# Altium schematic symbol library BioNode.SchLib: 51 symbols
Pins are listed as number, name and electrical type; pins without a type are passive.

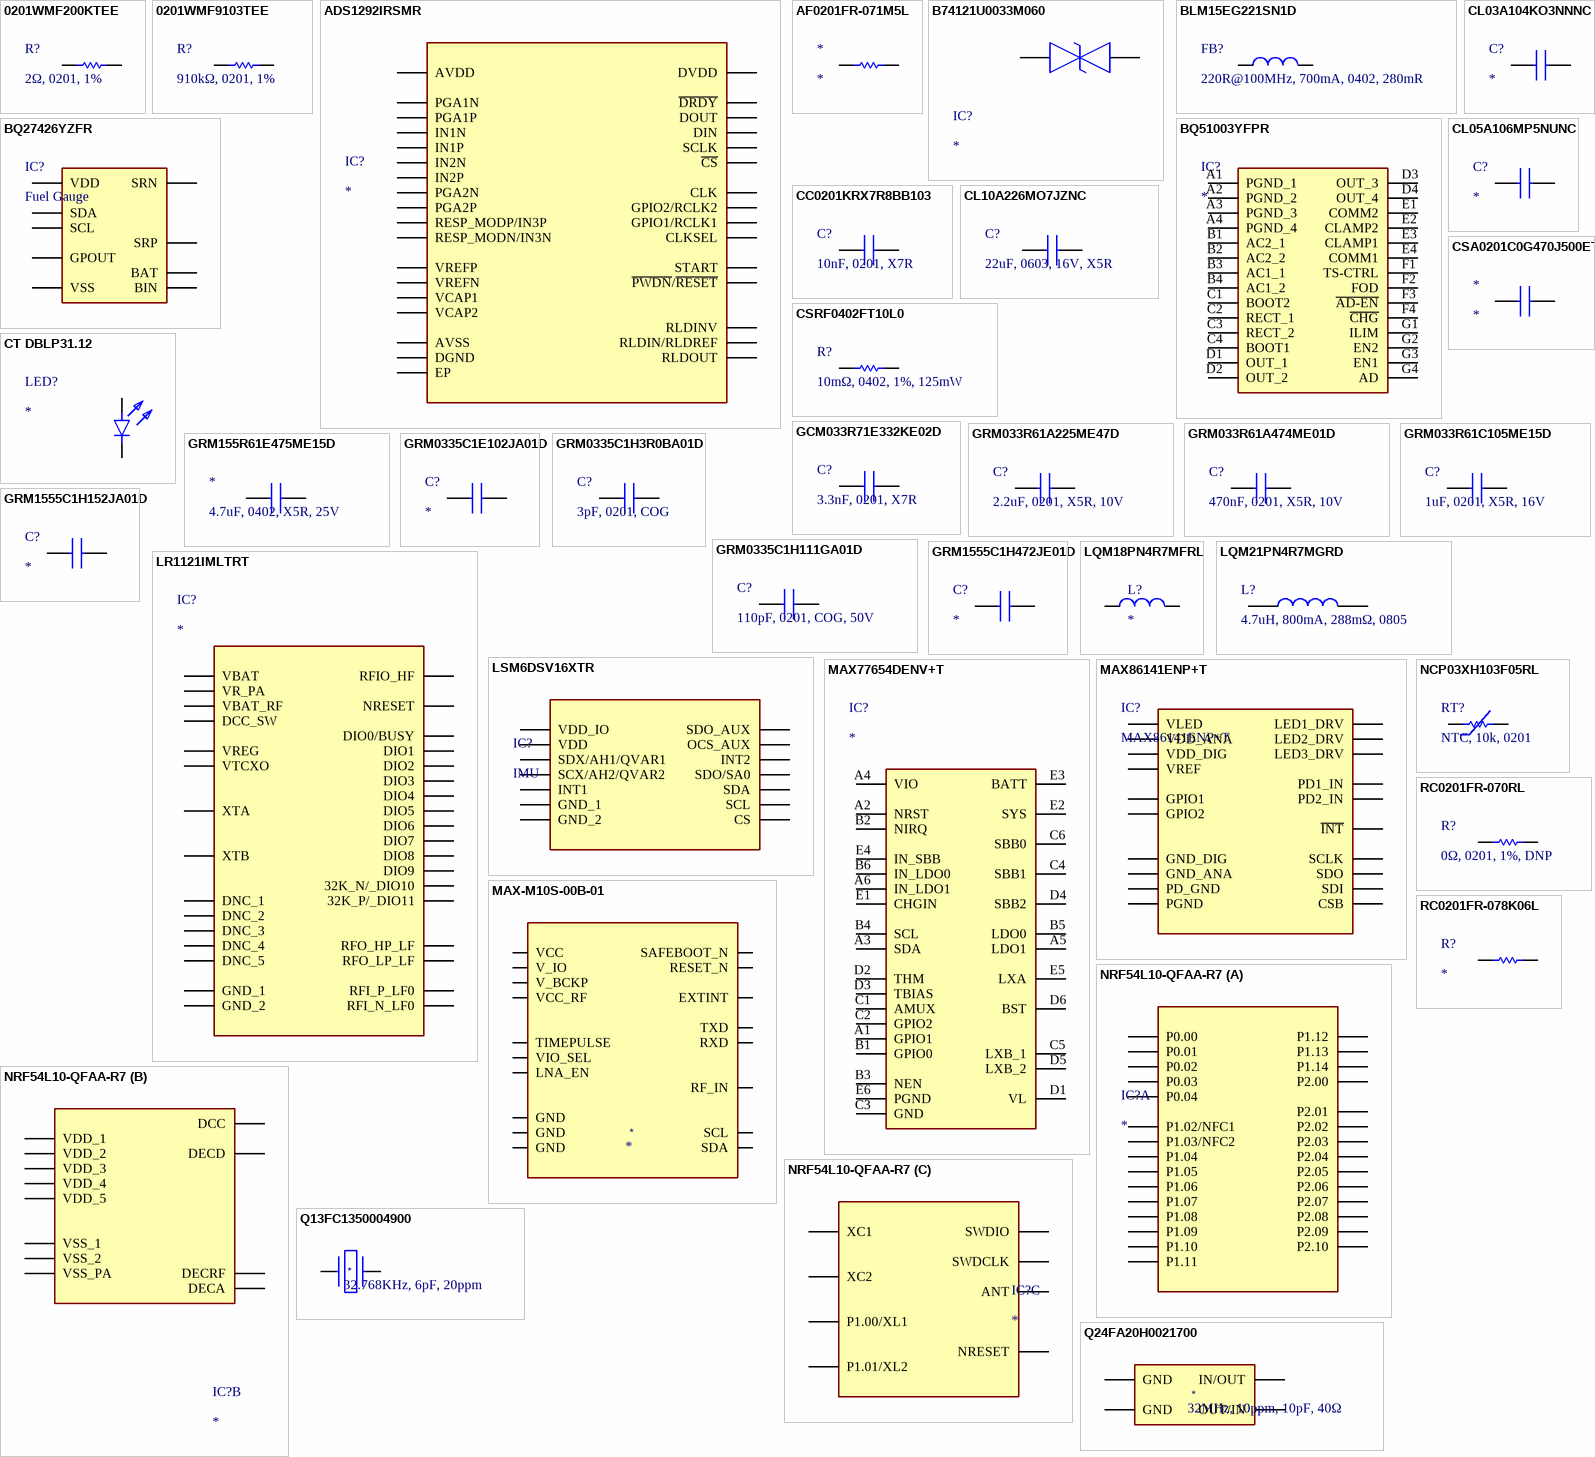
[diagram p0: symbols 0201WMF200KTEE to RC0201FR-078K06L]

## 0201WMF200KTEE
designator R?, comment 2Ω, 0201, 1%
2Ω ±1% 50mW 0201 Thick Film Resistor; Manufacturer_Name: UNI-ROYAL; Manu Part #: 0201WMF200KTEE
footprint 0201WMF200KTEE
pins: 1, 2

## 0201WMF9103TEE
designator R?, comment 910kΩ, 0201, 1%
RES 910kΩ ±1% 50mW 0201; Manufacturer_Name: UNI-ROYAL; Manu Part #: 0201WMF9103TEE
footprint 0201WMF9103TEE
pins: 1, 2

## ADS1292IRSMR
designator IC?
ECG AFE; Manufacturer_Name: Texas Instruments; Manufacturer_Part_Number: ADS1292IRSMR
footprint QFN40P400X400X100-33N-D
pins: 1 PGA1N, 2 PGA1P, 3 IN1N, 4 IN1P, 5 IN2N, 6 IN2P, 7 PGA2N, 8 PGA2P, 9 VREFP, 10 VREFN, 11 VCAP1, 12 AVDD, 13 AVSS, 14 CLKSEL, 15 ~{PWDN}/~{RESET}, 16 START, 17 CLK, 18 ~{CS}, 19 DIN, 20 SCLK, 21 DOUT, 22 ~{DRDY}, 23 DVDD, 24 DGND, 25 GPIO2/RCLK2, 26 GPIO1/RCLK1, 27 VCAP2, 28 RLDINV, 29 RLDIN/RLDREF, 30 RLDOUT, 31 RESP_MODP/IN3P, 32 RESP_MODN/IN3N, 33 EP

## AF0201FR-071M5L
designator *
1.5M, 0201. 1%; Manu Part #: AF0201FR-071M5L
footprint AF0201FR-071M5L
pins: 1, 2

## B74121U0033M060
designator IC?
-40℃~+125℃ 0.65pF 1 1nA 3.3V 5.2V 5V 7A@8/20us Bidirectional IEC 61000-4-2、IEC 61000-4-5 TVS 0201 ESD and Surge Protection (TVS/ESD) ROHS; Manufacturer_Name: TDK; Manu Part #: B74121U0033M060
footprint B74121U0033M060
pins: A1 I/O, B1 GND

## BLM15EG221SN1D
designator FB?, comment 220R@100MHz, 700mA, 0402, 280mR
BLM15_N1D Series EMI Suppression Filter 220+/-25% at 100MHz 700mA @85; Manufacturer_Name: Murata Electronics; Manu Part #: BLM15EG221SN1D
footprint NFZ15SG152SN10B
pins: 1, 2

## BQ27426YZFR
designator IC?, comment Fuel Gauge
Single cell System-Side Battery Fuel (Gas) Gauge w/Pre-programmed Chemistry Profile; Manufacturer_Name: Texas Instruments; Manu Part #: BQ27426YZFR
footprint BQ27426YZFR
pins: A1 GPOUT, A2 SDA, A3 SCL, B1 BIN, B2 VSS, B3 VDD, C1 SRP, C2 SRN, C3 BAT

## BQ51003YFPR
designator IC?
Integrated Circuit; Manufacturer_Name: Texas Instruments; Manufacturer_Part_Number: BQ51003YFPR
footprint BGA28C40P4X7_188X301X50
pins: A1 PGND_1, A2 PGND_2, A3 PGND_3, A4 PGND_4, B1 AC2_1, B2 AC2_2, B3 AC1_1, B4 AC1_2, C1 BOOT2, C2 RECT_1, C3 RECT_2, C4 BOOT1, D1 OUT_1, D2 OUT_2, D3 OUT_3, D4 OUT_4, E1 COMM2, E2 CLAMP2, E3 CLAMP1, E4 COMM1, F1 TS-CTRL, F2 FOD, F3 ~{AD-EN}, F4 ~{CHG}, G1 ILIM, G2 EN2, G3 EN1, G4 AD

## CC0201KRX7R8BB103
designator C?, comment 10nF, 0201, X7R
Manufacturer_Name: YAGEO; Manu Part #: CC0201KRX7R8BB103
footprint CL03A105MQ3CSNH
pins: 1, 2

## CL03A104KO3NNNC
designator C?
CAP CER 100nF 25V X5R 0201; Manufacturer_Name: SAMSUNG; Manu Part #: CL03A104KA3NNNC
footprint CL03A104KO3NNNC
pins: 1, 2

## CL05A106MP5NUNC
designator C?
10uF, 0402, X5R; Manufacturer_Name: SAMSUNG; Manu Part #: CL05A106MP5NUNC
footprint CL05A106MP5NUNC
pins: 1, 2

## CL10A226MO7JZNC
designator C?, comment 22uF, 0603, 16V, X5R
Multilayer Ceramic Capacitors MLCC - SMD/SMT 22uF+/-20% 16V X5R 1608; Manufacturer_Name: SAMSUNG; Manu Part #: CL10A226MO7JZNC
footprint CAPC1608X80N
pins: 1, 2

## CSA0201C0G470J500ET
designator *
47pF, 0201, COG, 5%; Manu Part #: CSA0201C0G470J500ET
footprint CSA0201C0G470J500ET
pins: 1, 2

## CSRF0402FT10L0
designator R?, comment 10mΩ, 0402, 1%, 125mW
RES 10mΩ ±1% 125mW 0402; Manufacturer_Name: Stackpole Electronics; Manu Part #: CSRF0402FT10L0
footprint CSRF0402FT10L0
pins: 1, 2

## CT DBLP31.12
designator LED?
Standard LEDs - SMD Green 536nm Firefly E2218; Manufacturer_Name: ams OSRAM; Manu Part #: CT DBLP31.12-6C5D-56-J6U6-20-R18
footprint CTDBLP31126C5D56J6U620R18
pins: 1 -VE, 2 +VE

## GCM033R71E332KE02D
designator C?, comment 3.3nF, 0201, X7R
Manufacturer_Name: Murata Electronics; Manu Part #: GCM033R71E332KE02D
footprint GCM033R71E332KE02D
pins: 1, 2

## GRM033R61A225ME47D
designator C?, comment 2.2uF, 0201, X5R, 10V
Manufacturer_Name: Murata Electronics; Manu Part #: GRM033R61A225ME47D
footprint GRM033R61A225ME47D
pins: 1, 2

## GRM033R61A474ME01D
designator C?, comment 470nF, 0201, X5R, 10V
470nF X5R ±20% 10V 0201 Ceramic Capacitors RoHS; Manufacturer_Name: muRata; Manu Part #: GRM033R61A474ME01D
footprint GRM033R61A474ME01D
pins: 1, 2

## GRM033R61C105ME15D
designator C?, comment 1uF, 0201, X5R, 16V
Manufacturer_Name: muRata; Manu Part #: GRM033R61C105ME15D
footprint GRM033R61C105ME15D
pins: 1, 2

## GRM155R61E475ME15D
designator *, comment 4.7uF, 0402, X5R, 25V
4.7uF ±20% 25V Ceramic Capacitor X5R 0402; Manu Part #: GRM155R61E475ME15D
footprint CL05A106MP5NUNC
pins: 1, 2

## GRM0335C1E102JA01D
designator C?
1nF, 0201, COG, 5%; Manufacturer_Name: Murata Electronics; Manu Part #: GRM0335C1E102JA01D
footprint GRM0335C1E102JA01D
pins: 1, 2

## GRM0335C1H3R0BA01D
designator C?, comment 3pF, 0201, COG
Manufacturer_Name: Murata Electronics; Manu Part #: GRM0335C1H3R0BA01D
footprint GRM0335C1H3R0BA01D
pins: 1, 2

## GRM0335C1H111GA01D
designator C?, comment 110pF, 0201, COG, 50V
110pF C0G ±2% 50V 0201 Ceramic Capacitors RoHS; Manu Part #: GRM0335C1H111GA01D
footprint GRM0335C1H111GA01D
pins: 1, 2

## GRM1555C1H152JA01D
designator C?
1.5nF, 0402, COG; Manufacturer_Name: Murata Electronics; Manu Part #: GRM1555C1H152JA01D
footprint GRM1555C1H152JA01D
pins: 1, 2

## GRM1555C1H472JE01D
designator C?
4.7nF, 0402, COG; Manufacturer_Name: Murata Electronics; Manu Part #: GRM1555C1H472JE01D
footprint GRM15x
pins: 1, 2

## LQM18PN4R7MFRL
designator L?
FIXED IND 4.7uH 620mA 440mΩ 0603; Manufacturer_Name: Murata Electronics; Manu Part #: LQM18PN4R7MFRL
footprint LQM18PH1R0MFRB
pins: 1, 2

## LQM21PN4R7MGRD
designator L?, comment 4.7uH, 800mA, 288mΩ, 0805
FIXED IND 4.7uH 800mA 288mΩ 0805; Manufacturer_Name: Murata Electronics; Manu Part #: LQM21PN4R7MGRD
footprint LQM21PHR47NG0D
pins: 1, 2

## LR1121IMLTRT
designator IC?
-108dBm -40℃~+85℃ 1.8V~3.7V 101.5Kbps 13dBm 150MHz~960MHz、1.9GHz~2.1GHz、2.4GHz~2.5GHz 26mA 7.8mA LoRa SPI transceiver QFN-32-EP(5x5) RF Transceiver ICs ROHS; Manufacturer_Name: SEMTECH; Manu Part #: LR1121IMLTRT
footprint QFN50P500X500X100-33N-D
pins: 1 VR_PA, 2 VBAT_RF, 3 VTCXO, 4 XTA, 5 XTB, 6 NRESET, 7 32K_P/_DIO11, 8 32K_N/_DIO10, 9 DIO9, 10 DIO8, 11 DIO7, 12 VREG, 13 GND_1, 14 DCC_SW, 15 VBAT, 16 DNC_1, 17 DNC_2, 18 DNC_3, 19 DIO6, 20 DIO5, 21 DIO4, 22 DIO3, 23 DIO2, 24 DIO1, 25 DIO0/BUSY, 26 RFIO_HF, 27 DNC_4, 28 DNC_5, 29 RFI_N_LF0, 30 RFI_P_LF0, 31 RFO_LP_LF, 32 RFO_HP_LF, 33 GND_2

## LSM6DSV16XTR
designator IC?, comment IMU
6-axis inertial measurement unit (IMU) and Al sensor with embedded sensor fusion, Qvar for high-end applications; Manufacturer_Name: STMicroelectronics; Manu Part #: LSM6DSV16XTR
footprint LSM6DSV16BXTR
pins: 1 SDO/SA0, 2 SDX/AH1/QVAR1, 3 SCX/AH2/QVAR2, 4 INT1, 5 VDD_IO, 6 GND_1, 7 GND_2, 8 VDD, 9 INT2, 10 OCS_AUX, 11 SDO_AUX, 12 CS, 13 SCL, 14 SDA

## MAX77654DENV+T
designator IC?
Power Management Specialised - PMIC Ultra Low Power PMIC w/ 3-Output SIMO + Linear Charger; Manufacturer_Name: Analog Devices; Manu Part #: MAX77654DENV+T
footprint BGA30C40P6X5_279X234X50
pins: A1 GPIO1, A2 NRST, A3 SDA, A4 VIO, A5 LDO1, A6 IN_LDO1, B1 GPIO0, B2 NIRQ, B3 NEN, B4 SCL, B5 LDO0, B6 IN_LDO0, C1 AMUX, C2 GPIO2, C3 GND, C4 SBB1, C5 LXB_1, C6 SBB0, D1 VL, D2 THM, D3 TBIAS, D4 SBB2, D5 LXB_2, D6 BST, E1 CHGIN, E2 SYS, E3 BATT, E4 IN_SBB, E5 LXA, E6 PGND

## MAX86141ENP+T
designator IC?
Optical Pulse Oximeter and Heart-Rate Sensor for Wearable Health; Manufacturer_Name: Analog Devices
footprint BGA20C40P5X4_205X185X50
pins: A1 VLED, A2 SCLK, A3 SDO, A4 SDI, A5 CSB, B1 LED3_DRV, B2 ~{INT}, B3 GPIO1, B4 GPIO2, B5 VREF, C1 LED2_DRV, C2 VDD_DIG, C3 GND_DIG, C4 GND_ANA, C5 PD_GND, D1 LED1_DRV, D2 VDD_ANA, D3 PGND, D4 PD2_IN, D5 PD1_IN

## MAX-M10S-00B-01
designator *
MAX-M10 RF Receiver BeiDou, Galileo, GLONASS, GPS, GNSS 1.561GHz, 1.575GHz, 1.602GHz -167dBm 921.6kbps Module; Manufacturer: U-BLOX; Manu Part #: MAX-M10S-00B-01
footprint MAX-M10S-00B-01
pins: 1 GND, 2 TXD, 3 RXD, 4 TIMEPULSE, 5 EXTINT, 6 V_BCKP, 7 V_IO, 8 VCC, 9 RESET_N, 10 GND, 11 RF_IN, 12 GND, 13 LNA_EN, 14 VCC_RF, 15 VIO_SEL, 16 SDA, 17 SCL, 18 SAFEBOOT_N

## NCP03XH103F05RL
designator RT?, comment NTC, 10k, 0201
THERMISTOR NTC 10kΩ 3380K 0201; Manufacturer_Name: Murata Electronics; Manu Part #: NCP03XH103F05RL
footprint NCP03XH103F05RL
pins: 1, 2

## NRF54L10-QFAA-R7
designator IC?
IC RF TxRx + MCU 802.15.4, Bluetooth Bluetooth v6.0, Matter, Thread 48-VFQFN Exposed Pad; Manufacturer_Name: Nordic Semiconductor; Manu Part #: NRF54L10-QFAA-R7
footprint NRF54L10-QFAA-R7
part A pins: 3 P1.02/NFC1, 4 P1.03/NFC2, 5 P1.04, 6 P1.05, 7 P1.06, 8 P1.07, 9 P1.08, 11 P2.00, 12 P2.01, 13 P2.02, 14 P2.03, 15 P2.04, 16 P2.05, 17 P2.06, 18 P2.07, 19 P2.08, 20 P2.09, 21 P2.10, 23 P0.00, 24 P0.01, 27 P0.02, 28 P0.03, 29 P0.04, 37 P1.09, 38 P1.10, 39 P1.11, 40 P1.12, 41 P1.13, 42 P1.14
part B pins: 10 VDD_1, 22 VDD_2, 32 VSS_PA, 33 DECRF, 36 VDD_3, 43 DECA, 44 VSS_1, 45 DECD, 46 DCC, 47 VDD_4, 48 VDD_5, 49 VSS_2
part C pins: 1 P1.00/XL1, 2 P1.01/XL2, 25 SWDIO, 26 SWDCLK, 30 NRESET, 31 ANT, 34 XC1, 35 XC2

## Q13FC1350004900
designator *, comment 32.768KHz, 6pF, 20ppm
-40℃~+85℃ 32.768kHz 6pF 70kΩ Crystal Oscillator ±20ppm SMD3215-2P Crystals ROHS; Manufacturer: Seiko Epson; Manu Part #: Q13FC13500049
footprint Q13FC1350004900
pins: 1, 2

## Q24FA20H0021700
designator *, comment 32MHz, 10ppm, 10pF, 40Ω
-40℃~+85℃ 10pF 32MHz 40Ω Crystal Oscillator ±10ppm ±20ppm SMD2520-4P Crystals ROHS; Manufacturer: Seiko Epson; Manu Part #: Q24FA20H00217
footprint Q24FA20H0021700
pins: 1 IN/OUT, 2 GND, 3 OUT/IN, 4 GND

## RC0201FR-070RL
designator R?, comment 0Ω, 0201, 1%, DNP
RES 0Ω ±1% 50mW 0201; Manufacturer_Name: YAGEO; Manu Part #: RC0201FR-070RL
footprint RC0201FR-070RL
pins: 1, 2

## RC0201FR-078K06L
designator R?
8.06k, 0201, 1%; Manufacturer_Name: Yageo Group; Manu Part #: RC0201FR-078K06L
footprint RC0201FR-078K06L
pins: 1, 2

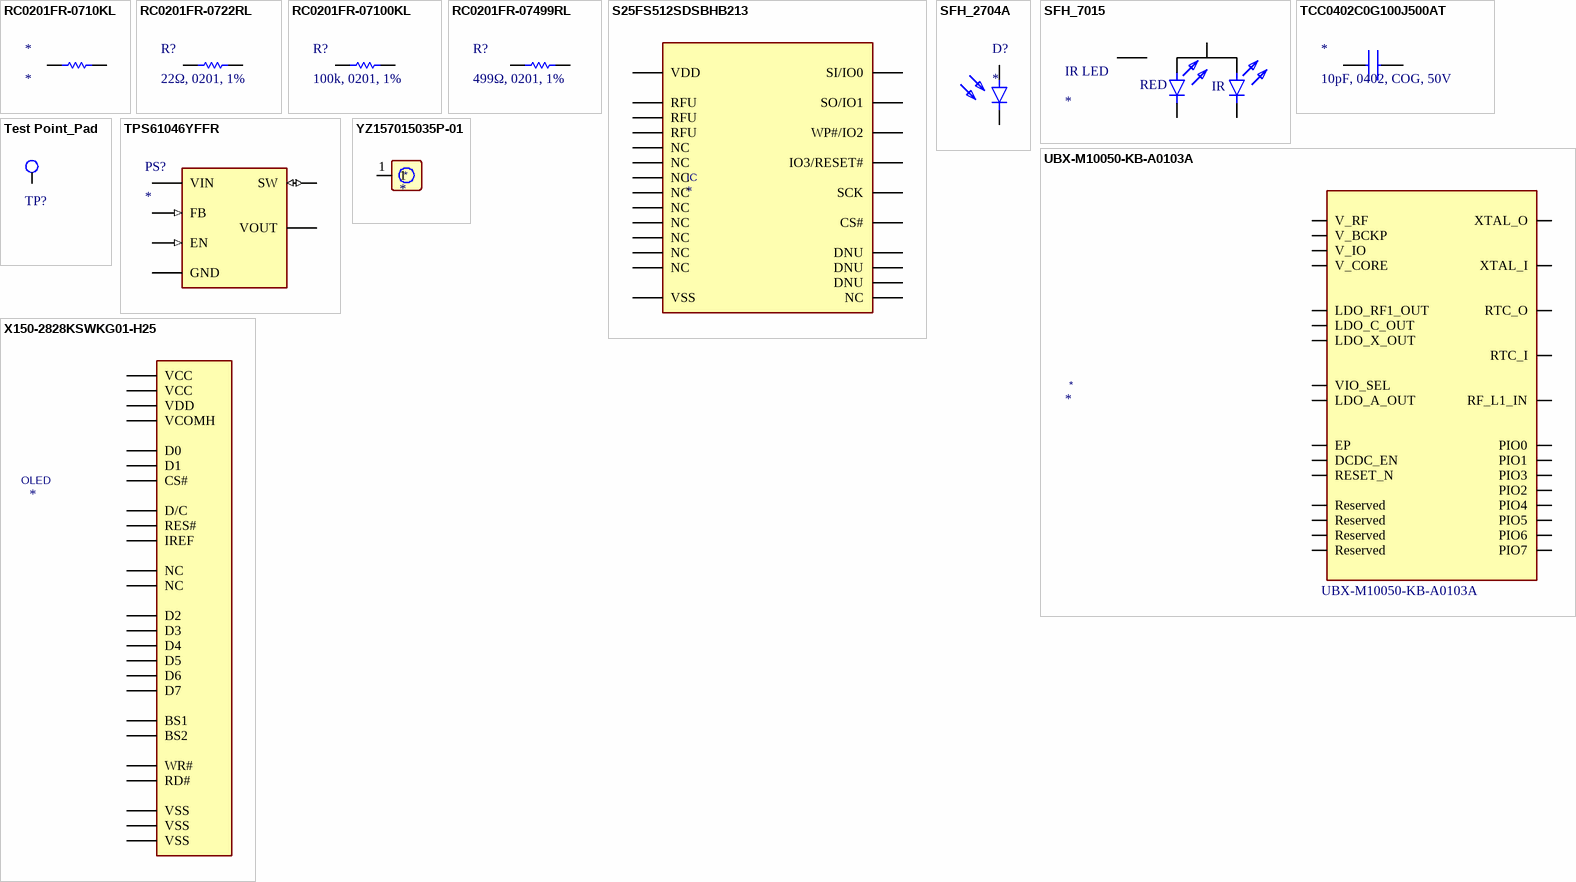
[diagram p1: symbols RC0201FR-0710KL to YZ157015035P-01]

## RC0201FR-0710KL
designator *
10k, 0201, 1%; Manu Part #: RC0201FR-0710KL
footprint RC0201FR-0710KL
pins: 1, 2

## RC0201FR-0722RL
designator R?, comment 22Ω, 0201, 1%
RES 22Ω ±1% 50mW 0201; Manu Part #: RC0201FR-0722RL
footprint AF0201FR-071M5L
pins: 1, 2

## RC0201FR-07100KL
designator R?, comment 100k, 0201, 1%
Manufacturer_Name: Yageo Group; Manu Part #: RC0201FR-07100KL
footprint RC0201FR-0710KL
pins: 1, 2

## RC0201FR-07499RL
designator R?, comment 499Ω, 0201, 1%
50mW 499Ω 25V Thick Film Resistor ±1% ±200ppm/℃ 0201 Chip Resistor - Surface Mount RoHS; Manufacturer_Name: Yageo Group; Manu Part #: RC0201FR-07499RL
footprint RC0201FR-07499RL
pins: 1, 2

## S25FS512SDSBHB213
designator IC
-40℃~+105℃ 1.7V~2V 512Mbit SPI TBGA-24 NOR FLASH ROHS; Manufacturer: Infineon/Cypress Semicon; Manu Part #: S25FS512SDSBHB213
footprint S25FS512SDSBHB213
pins: A2 NC, A3 NC, A4 RFU, A5 NC, B1 DNU, B2 SCK, B3 VSS, B4 VDD, B5 NC, C1 DNU, C2 CS#, C3 RFU, C4 WP#/IO2, C5 NC, D1 DNU, D2 SO/IO1, D3 SI/IO0, D4 IO3/RESET#, D5 NC, E1 NC, E2 NC, E3 NC, E4 RFU, E5 NC

## SFH_2704A
designator D?
Photodiodes FOR VITAL SIGNALMONITORING ,920nm ,400nm ~ 1100nm ,150pA ,6v .; Manufacturer_Name: ams OSRAM; Manu Part #: SFH 2704A
footprint SFH2704A
pins: 1 K, 2 A

## SFH_7015
designator IR LED
Red (655 nm) and Infrared Emitter (940 nm); Manufacturer_Name: ams OSRAM
footprint SFH7015
pins: 1 NC, 2 RED -VE, 3 VCC, 4 IR -VE

## TCC0402C0G100J500AT
designator *, comment 10pF, 0402, COG, 50V
10pF ±5% 50V Ceramic Capacitor C0G 0402; Manu Part #: TCC0402C0G100J500AT
footprint GRM15x
pins: 1, 2

## Test Point_Pad
designator TP?
2mm Pad
footprint Test_Pad
pins: 0

## TPS61046YFFR
designator PS?
28-V Output Voltage Boost Converter in WCSP Package; Manufacturer_Name: Texas Instruments; Manu Part #: TPS61046YFFR
footprint BGA6C40P2X3_88X123X62
pins: A1 VIN (power), A2 GND (power), B1 FB (in), B2 SW (io), C1 EN (in), C2 VOUT (power)

## UBX-M10050-KB-A0103A
designator *  Manu Part #: UBX-M10050-KB-A0103A
UBX-M10050-KB-A0103A; QFN-28_L4.0-W4.0-P0.40-BL-EP2.7; U-BLOX(优北罗); ki_keywords: C44571738 QFN-28_L4.0-W4.0-P0.40-BL-EP2.7 U-BLOX(优北罗) UBX-M10050-KB-A0103A
footprint UBX-M10050-KB-A0103A (Footprint not found)
pins: 1 Reserved, 2 LDO_RF1_OUT, 3 Reserved, 4 DCDC_EN, 5 PIO6, 6 PIO7, 7 XTAL_O, 8 XTAL_I, 9 LDO_X_OUT, 10 VIO_SEL, 11 V_BCKP, 12 V_IO, 13 LDO_A_OUT, 14 V_CORE, 15 LDO_C_OUT, 16 PIO0, 17 PIO1, 18 PIO3, 19 PIO2, 20 Reserved, 21 RTC_I, 22 RTC_O, 23 RESET_N, 24 PIO5, 25 PIO4, 26 Reserved, 27 V_RF, 28 RF_L1_IN, 29 EP

## X150-2828KSWKG01-H25
designator OLED
-40℃~+70℃ 1.54 100cd/m2 128x128 26.855x26.855mm Passive (PMOLED) SH1107 chip White - OLED Display ROHS; Manufacturer: Newvisio; Manu Part #: X150-2828KSWKG01-H25
footprint X150-2828KSWKG01-H25
pins: 1 VSS, 2 VCC, 3 VCOMH, 4 NC, 5 VDD, 6 NC, 7 BS1, 8 BS2, 9 VSS, 10 IREF, 11 CS#, 12 RES#, 13 D/C, 14 WR#, 15 RD#, 16 D0, 17 D1, 18 D2, 19 D3, 20 D4, 21 D5, 22 D6, 23 D7, 24 VCC, 25 VSS

## YZ157015035P-01
designator *
-40℃~+85℃ 10000 times 12V 1A 1P 2.2mm 3.5mm 50mΩ Brass Gold Pogo Pin SMD,D=2mm Pogo Pin Spring Probe Connector ROHS; Manufacturer: Xinyangze; Manu Part #: YZ157015035P-01
footprint YZ157015035P-01
pins: 1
